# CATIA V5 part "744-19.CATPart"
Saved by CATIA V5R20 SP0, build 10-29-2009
Part number: 744-19
Revision: TUTTO
Definition: NON CONOSCIUTO
Nomenclature: 744-19
Source: Unknown
Bounding box of the stored display mesh (mm): x -20 to 20, y -21 to 20, z -23 to 20
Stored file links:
  C:\Users\Utente\Desktop\IO LAVORO\3D X SITO CF\X SITO\744\744-19.CATPart
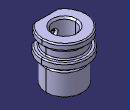
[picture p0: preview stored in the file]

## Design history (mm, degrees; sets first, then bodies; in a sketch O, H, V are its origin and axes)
Body1 "744-19 sol1" (main body)
  Solid1: solid without history
Body2 "IDV1M8_Ingrassatore-1"
  Solid2: solid without history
